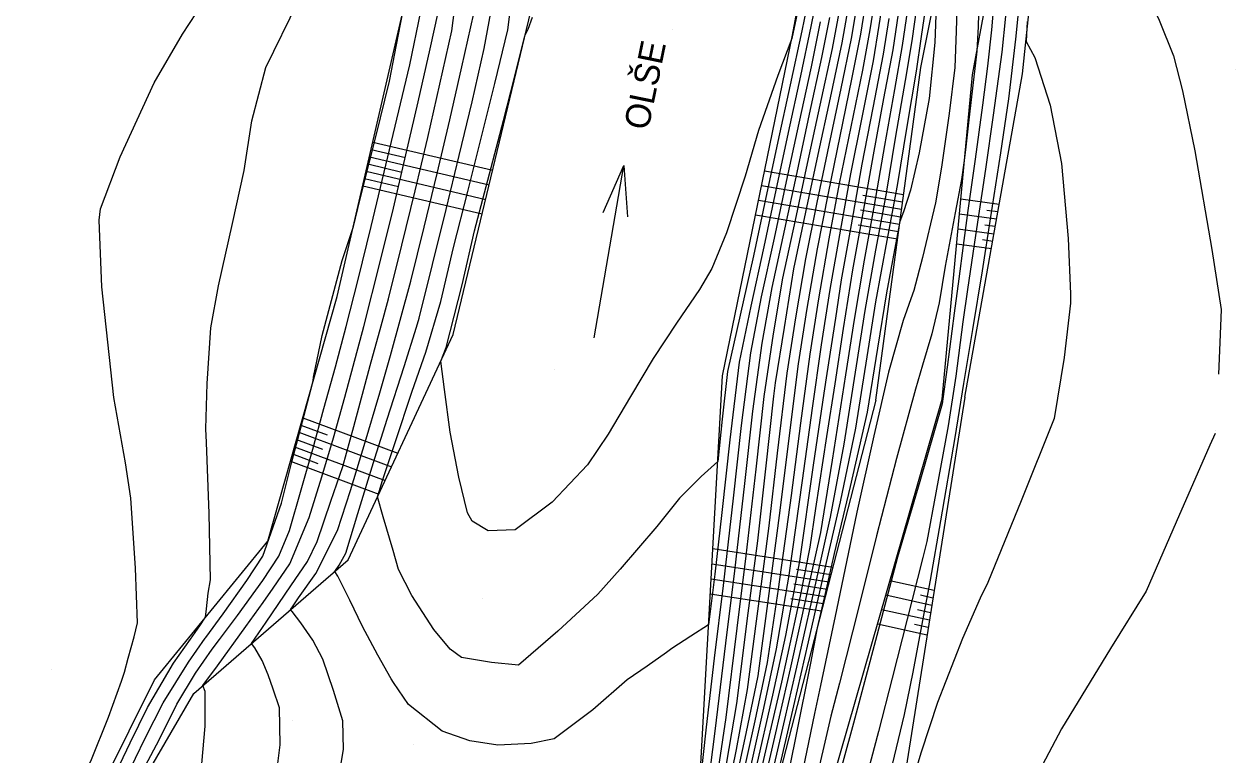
# Model space of a CAD drawing. Extents: x -448957 to -448612, y -1107690 to -1107245.
# Drawn here: x -448666.49 to -448617.96, y -1107347.3 to -1107318.02 of the extents above; entities that cross this region are included whole.
import ezdxf

# ---------------------------------------------------------------- set-up
doc = ezdxf.new("R2010")
doc.units = 0
for name, color, linetype in [('Default', 7, 'Continuous'), ('Vrstva 1', 7, 'Continuous'), ('Vrstva 14', 7, 'Continuous'), ('Vrstva 15', 7, 'Continuous'), ('Vrstva 16', 7, 'Continuous'), ('Vrstva 17', 7, 'Continuous'), ('Vrstva 45', 7, 'Continuous')]:
    doc.layers.add(name, color=color, linetype=linetype)

# ---------------------------------------------------------------- blocks, each defined once
blk = doc.blocks.new('POINT_DISPLAY')
at = {"layer": 'Default'}
blk.add_line((0, 0), (0, 0), dxfattribs=at)
blk = doc.blocks.new('TOK')
at = {"layer": 'Default'}
for p, q in [((-5, 50), (0, 70)), ((0, 0), (0, 70)), ((0, 70), (5, 50))]:
    blk.add_line(p, q, dxfattribs=at)

msp = doc.modelspace()

# ---------------------------------------------------------------- linework, layer by layer
at = {"layer": 'Vrstva 14'}
for p, q in [((-448635.721, -1107318.467), (-448634.176, -1107310.229)), ((-448630.579, -1107319.751), (-448628.858, -1107311.238)), ((-448628.507, -1107320.045), (-448626.884, -1107311.34)), ((-448626.501, -1107320.009), (-448625.591, -1107311.34)), ((-448653.948, -1107328.929), (-448651.01, -1107316.15)), ((-448649.301, -1107330.46), (-448646.198, -1107317.516)), ((-448638.523, -1107332.119), (-448635.721, -1107318.467)), ((-448632.378, -1107333.085), (-448630.579, -1107319.751)), ((-448629.722, -1107333.044), (-448628.507, -1107320.045)), ((-448628.814, -1107332.973), (-448626.501, -1107320.009)), ((-448656.73, -1107338.733), (-448653.948, -1107328.929)), ((-448653.513, -1107339.486), (-448649.301, -1107330.46)), ((-448639.5, -1107349.716), (-448638.523, -1107332.119)), ((-448632.378, -1107333.085), (-448636.968, -1107350.917)), ((-448635.081, -1107351.7), (-448629.722, -1107333.044)), ((-448628.814, -1107332.973), (-448631.997, -1107353.013)), ((-448661.274, -1107344.294), (-448656.73, -1107338.733)), ((-448659.693, -1107344.838), (-448653.513, -1107339.486)), ((-448665.508, -1107352.833), (-448661.274, -1107344.294)), ((-448664.543, -1107353.162), (-448659.693, -1107344.838))]:
    msp.add_line(p, q, dxfattribs=at)
at = {"layer": 'Vrstva 15'}
for p, q in [((-448652.527, -1107322.747), (-448647.722, -1107323.875)), ((-448652.661, -1107323.332), (-448647.862, -1107324.458)), ((-448652.594, -1107323.039), (-448651.223, -1107323.361)), ((-448652.728, -1107323.624), (-448651.359, -1107323.946)), ((-448652.863, -1107324.209), (-448651.495, -1107324.53)), ((-448652.796, -1107323.916), (-448648.002, -1107325.042)), ((-448631.268, -1107324.858), (-448636.839, -1107323.912)), ((-448652.93, -1107324.501), (-448648.142, -1107325.625)), ((-448631.348, -1107325.453), (-448636.959, -1107324.5)), ((-448631.429, -1107326.048), (-448637.08, -1107325.088)), ((-448631.308, -1107325.156), (-448632.9, -1107324.885)), ((-448627.436, -1107325.247), (-448628.974, -1107325.039)), ((-448631.509, -1107326.643), (-448637.201, -1107325.676)), ((-448631.388, -1107325.751), (-448632.992, -1107325.478)), ((-448627.541, -1107325.839), (-448629.03, -1107325.637)), ((-448627.488, -1107325.543), (-448627.928, -1107325.483)), ((-448631.469, -1107326.346), (-448633.083, -1107326.071)), ((-448627.647, -1107326.43), (-448629.086, -1107326.234)), ((-448627.594, -1107326.134), (-448628.019, -1107326.076)), ((-448627.699, -1107326.725), (-448628.11, -1107326.669)), ((-448627.752, -1107327.021), (-448629.141, -1107326.832)), ((-448655.329, -1107333.796), (-448651.52, -1107335.215)), ((-448655.493, -1107334.375), (-448651.774, -1107335.76)), ((-448655.411, -1107334.085), (-448654.349, -1107334.481)), ((-448655.658, -1107334.954), (-448652.029, -1107336.306)), ((-448655.576, -1107334.664), (-448654.539, -1107335.051)), ((-448655.74, -1107335.244), (-448654.729, -1107335.62)), ((-448655.822, -1107335.533), (-448652.283, -1107336.851)), ((-448634.105, -1107339.796), (-448638.908, -1107339.052)), ((-448634.256, -1107340.38), (-448638.941, -1107339.654)), ((-448634.181, -1107340.088), (-448635.553, -1107339.875)), ((-448634.406, -1107340.964), (-448638.975, -1107340.256)), ((-448630.045, -1107340.721), (-448631.814, -1107340.328)), ((-448634.331, -1107340.672), (-448635.67, -1107340.465)), ((-448634.556, -1107341.548), (-448639.008, -1107340.858)), ((-448634.481, -1107341.256), (-448635.787, -1107341.054)), ((-448630.139, -1107341.315), (-448631.98, -1107340.906)), ((-448630.092, -1107341.018), (-448630.597, -1107340.906)), ((-448630.233, -1107341.909), (-448632.146, -1107341.484)), ((-448630.186, -1107341.612), (-448630.712, -1107341.495)), ((-448630.328, -1107342.502), (-448632.312, -1107342.061)), ((-448630.28, -1107342.205), (-448630.827, -1107342.084))]:
    msp.add_line(p, q, dxfattribs=at)
at = {"layer": 'Vrstva 16'}
for points in [[(-448629.106, -1107316.523), (-448629.157, -1107318.305), (-448629.22, -1107319.755), (-448629.449, -1107321.594), (-448629.744, -1107323.748), (-448629.994, -1107325.182), (-448630.505, -1107327.371), (-448630.863, -1107328.699), (-448630.908, -1107328.847), (-448631.284, -1107329.89), (-448631.877, -1107331.97), (-448632.455, -1107334.512), (-448633.135, -1107337.575), (-448633.956, -1107341.492), (-448634.593, -1107344.517), (-448634.838, -1107345.644), (-448635.47, -1107348.671)], [(-448634.697, -1107316.72), (-448634.979, -1107318.108), (-448635.391, -1107320.087), (-448635.886, -1107322.356), (-448636.383, -1107324.678), (-448636.866, -1107326.949), (-448637.392, -1107329.316), (-448637.859, -1107331.566), (-448638.229, -1107334.684), (-448638.543, -1107337.593), (-448638.834, -1107340.058), (-448639.077, -1107342.091), (-448639.783, -1107342.548), (-448640.547, -1107343.043), (-448640.766, -1107343.197), (-448641.533, -1107343.748), (-448642.341, -1107344.302), (-448643.718, -1107345.501), (-448645.268, -1107346.657), (-448646.186, -1107346.846), (-448647.512, -1107346.918), (-448648.644, -1107346.739), (-448649.754, -1107346.356), (-448651.09, -1107345.278), (-448651.698, -1107344.404), (-448651.792, -1107344.262), (-448652.329, -1107343.304), (-448652.943, -1107342.156), (-448653.443, -1107341.1), (-448653.927, -1107340.142), (-448654.047, -1107339.948), (-448653.869, -1107339.696), (-448653.612, -1107339.218), (-448653.12, -1107337.636), (-448652.447, -1107335.416), (-448651.951, -1107333.844), (-448651.274, -1107331.737), (-448650.771, -1107330.167), (-448650.663, -1107329.804), (-448650.135, -1107327.65), (-448649.586, -1107325.446), (-448649.068, -1107323.289), (-448648.553, -1107321.135), (-448648.062, -1107319.001), (-448647.632, -1107316.676)], [(-448662.412, -1107348.242), (-448661.639, -1107346.632), (-448660.924, -1107345.213), (-448659.909, -1107343.584), (-448659.234, -1107342.629), (-448659.214, -1107342.601), (-448658.521, -1107341.652), (-448657.573, -1107340.317), (-448656.932, -1107339.341), (-448656.178, -1107337.212), (-448655.769, -1107335.565), (-448655.34, -1107333.946), (-448654.937, -1107332.414), (-448654.92, -1107332.301), (-448654.899, -1107332.173), (-448654.55, -1107330.499), (-448653.755, -1107327.486), (-448653.305, -1107326.131), (-448653.126, -1107325.403), (-448652.941, -1107324.648), (-448652.41, -1107322.53), (-448651.854, -1107320.303), (-448651.576, -1107318.852), (-448651.329, -1107317.537)], [(-448633.126, -1107317.166), (-448633.371, -1107318.595), (-448633.78, -1107320.603), (-448634.262, -1107322.875), (-448634.744, -1107325.173), (-448635.203, -1107327.425), (-448635.597, -1107329.794), (-448635.95, -1107332.008), (-448636.331, -1107335.215), (-448636.664, -1107338.121), (-448636.788, -1107339.044), (-448637.172, -1107341.943), (-448637.526, -1107344.687), (-448637.968, -1107347.084), (-448638.444, -1107349.382)], [(-448631.487, -1107317.61), (-448631.7, -1107319.047), (-448632.067, -1107321.003), (-448632.491, -1107323.26), (-448632.908, -1107325.665), (-448633.309, -1107327.872), (-448633.686, -1107330.214), (-448634.027, -1107332.429), (-448634.356, -1107334.547), (-448634.794, -1107337.436), (-448635.017, -1107338.98), (-448635.41, -1107340.943), (-448635.935, -1107343.353), (-448636.164, -1107344.395), (-448636.757, -1107346.965), (-448637.451, -1107349.97)], [(-448626.316, -1107317.915), (-448626.365, -1107318.711), (-448626.015, -1107319.352), (-448625.399, -1107321.27), (-448624.939, -1107323.608), (-448624.673, -1107326.604), (-448624.587, -1107328.827), (-448624.585, -1107329.204), (-448624.842, -1107331.382), (-448625.243, -1107333.824), (-448626.562, -1107337.126), (-448627.898, -1107340.389), (-448628.207, -1107341.018), (-448628.903, -1107342.638), (-448629.907, -1107345.198), (-448630.567, -1107347.19), (-448631.215, -1107349.365)]]:
    msp.add_lwpolyline(points, dxfattribs=at)
at = {"layer": 'Vrstva 17'}
for points in [[(-448617.964, -1107313.829), (-448618.273, -1107313.944), (-448619.544, -1107314.14), (-448620.66, -1107314.171), (-448621.165, -1107314.233), (-448622.028, -1107314.546), (-448621.957, -1107315.886), (-448621.031, -1107317.86), (-448620.462, -1107319.291), (-448620.091, -1107320.697), (-448619.61, -1107323.098), (-448618.918, -1107327.048), (-448618.552, -1107329.451), (-448618.602, -1107330.773), (-448618.658, -1107332.053)], [(-448656.419, -1107348.395), (-448656.237, -1107346.894), (-448656.263, -1107345.417), (-448656.52, -1107344.673), (-448656.722, -1107344.095), (-448656.959, -1107343.525), (-448657.245, -1107343.019), (-448657.384, -1107342.839), (-448656.801, -1107341.979), (-448655.813, -1107340.533), (-448655.141, -1107339.558), (-448654.748, -1107338.746), (-448654.203, -1107337.131), (-448653.729, -1107335.747), (-448653.292, -1107334.149), (-448652.629, -1107331.705), (-448652.186, -1107330.115), (-448651.892, -1107329.031), (-448651.359, -1107326.879), (-448650.823, -1107324.694), (-448650.326, -1107322.557), (-448649.837, -1107320.428), (-448649.36, -1107318.294), (-448649.07, -1107315.999)], [(-448628.23, -1107316.081), (-448628.276, -1107318.113), (-448628.33, -1107319.097), (-448628.384, -1107319.57), (-448628.48, -1107320.353), (-448628.655, -1107321.858), (-448628.788, -1107323.054), (-448628.859, -1107323.583), (-448628.947, -1107324.241), (-448629.202, -1107325.586), (-448629.602, -1107327.725), (-448629.849, -1107329.188), (-448630.142, -1107330.433), (-448630.505, -1107331.685), (-448630.797, -1107332.647), (-448631.554, -1107335.42), (-448632.354, -1107338.528), (-448633.048, -1107341.316), (-448633.839, -1107344.424), (-448634.184, -1107345.747), (-448634.881, -1107348.762)], [(-448627.534, -1107315.743), (-448627.745, -1107318.25), (-448627.906, -1107319.699), (-448628.111, -1107321.267), (-448628.405, -1107323.426), (-448628.578, -1107324.652), (-448628.694, -1107325.486), (-448628.879, -1107326.888), (-448629.06, -1107328.226), (-448629.244, -1107329.597), (-448629.526, -1107331.77), (-448629.728, -1107333.229), (-448630.622, -1107336.345), (-448631.507, -1107339.38), (-448632.34, -1107342.515), (-448633.28, -1107346.036), (-448634.134, -1107349.162)], [(-448635.06, -1107316.91), (-448635.349, -1107318.287), (-448635.811, -1107320.45), (-448636.307, -1107322.718), (-448636.8, -1107325.035), (-448637.283, -1107327.306), (-448637.817, -1107329.687), (-448638.315, -1107331.946), (-448638.53, -1107333.844), (-448638.713, -1107335.542), (-448639.376, -1107336.147), (-448640.239, -1107337.022), (-448641.154, -1107338.146), (-448642.616, -1107339.866), (-448643.51, -1107340.867), (-448645.112, -1107342.346), (-448646.689, -1107343.707), (-448647.776, -1107343.604), (-448648.973, -1107343.404), (-448649.423, -1107343.063), (-448650.075, -1107342.283), (-448650.968, -1107340.92), (-448651.493, -1107339.87), (-448651.716, -1107339.114), (-448652.105, -1107337.765), (-448652.335, -1107336.962), (-448652.258, -1107336.708), (-448652.149, -1107336.351), (-448651.628, -1107334.787), (-448650.949, -1107332.724), (-448650.404, -1107331.168), (-448649.805, -1107329.133), (-448649.294, -1107326.973), (-448648.721, -1107324.733), (-448648.181, -1107322.584), (-448647.64, -1107320.392), (-448647.12, -1107318.251), (-448646.907, -1107316.567)], [(-448667.516, -1107353.349), (-448666.237, -1107351.73), (-448665.263, -1107350.375), (-448664.557, -1107348.977), (-448663.821, -1107347.557), (-448663.111, -1107345.787), (-448662.585, -1107344.345), (-448662.505, -1107344.114), (-448662.472, -1107343.99), (-448662.32, -1107343.423), (-448662.081, -1107342.57), (-448661.948, -1107342.013), (-448662.027, -1107339.815), (-448662.213, -1107337.02), (-448662.425, -1107335.598), (-448662.903, -1107332.976), (-448663.381, -1107328.546), (-448663.491, -1107325.878), (-448663.429, -1107325.418), (-448662.646, -1107323.333), (-448661.288, -1107320.368), (-448660.143, -1107318.417), (-448659.03, -1107316.692)], [(-448659.377, -1107347.66), (-448659.245, -1107346.147), (-448659.236, -1107344.757), (-448659.33, -1107344.524), (-448658.741, -1107343.728), (-448657.613, -1107342.161), (-448656.922, -1107341.19), (-448656.521, -1107340.62), (-448655.855, -1107339.642), (-448655.068, -1107337.785), (-448654.565, -1107336.161), (-448654.098, -1107334.596), (-448653.645, -1107332.973), (-448653.308, -1107331.728), (-448652.885, -1107330.132), (-448652.234, -1107327.547), (-448651.703, -1107325.4), (-448651.203, -1107323.256), (-448650.705, -1107321.128), (-448650.225, -1107319.012), (-448649.761, -1107316.875)], [(-448632.76, -1107316.989), (-448632.999, -1107318.42), (-448633.348, -1107320.231), (-448633.822, -1107322.505), (-448634.294, -1107324.788), (-448634.734, -1107327.027), (-448635.139, -1107329.412), (-448635.489, -1107331.627), (-448635.863, -1107334.612), (-448636.22, -1107337.514), (-448636.719, -1107341.231), (-448637.099, -1107344.132), (-448637.584, -1107346.451), (-448638.234, -1107349.477)], [(-448632.395, -1107316.812), (-448632.626, -1107318.245), (-448632.915, -1107319.859), (-448633.382, -1107322.134), (-448633.845, -1107324.403), (-448634.266, -1107326.628), (-448634.681, -1107329.031), (-448635.027, -1107331.246), (-448635.394, -1107334.009), (-448635.776, -1107336.908), (-448636.293, -1107340.668), (-448636.733, -1107343.596), (-448637.229, -1107345.939), (-448637.892, -1107348.96)], [(-448632.029, -1107316.635), (-448632.254, -1107318.069), (-448632.483, -1107319.487), (-448632.942, -1107321.764), (-448633.395, -1107324.018), (-448633.797, -1107326.23), (-448634.223, -1107328.649), (-448634.566, -1107330.865), (-448634.926, -1107333.406), (-448635.332, -1107336.301), (-448635.868, -1107340.105), (-448636.368, -1107343.059), (-448636.875, -1107345.428), (-448637.55, -1107348.442)], [(-448663.068, -1107348.554), (-448662.25, -1107346.826), (-448661.548, -1107345.401), (-448660.502, -1107343.623), (-448659.825, -1107342.668), (-448659.452, -1107342.125), (-448659.222, -1107341.783), (-448659.192, -1107341.457), (-448659.123, -1107340.816), (-448659.03, -1107340.284), (-448659.074, -1107337.63), (-448659.185, -1107334.79), (-448659.211, -1107334.24), (-448659.162, -1107332.416), (-448659.016, -1107330.191), (-448658.705, -1107328.505), (-448658.144, -1107326.014), (-448657.672, -1107323.879), (-448657.377, -1107321.891), (-448656.813, -1107319.76), (-448655.517, -1107317.118)], [(-448662.067, -1107348.559), (-448661.083, -1107346.696), (-448660.378, -1107345.273), (-448659.624, -1107344.024), (-448658.953, -1107343.068), (-448658.672, -1107342.675), (-448657.946, -1107341.715), (-448656.933, -1107340.317), (-448656.283, -1107339.336), (-448655.856, -1107338.31), (-448655.398, -1107336.675), (-448654.934, -1107335.053), (-448654.484, -1107333.416), (-448654.022, -1107331.751), (-448653.595, -1107330.138), (-448653.118, -1107328.259), (-448652.592, -1107326.126), (-448652.072, -1107323.952), (-448651.558, -1107321.829), (-448651.04, -1107319.657), (-448650.603, -1107317.512)], [(-448635.423, -1107317.1), (-448635.733, -1107318.532), (-448635.747, -1107318.596), (-448636.306, -1107320.08), (-448637.077, -1107322.276), (-448637.607, -1107324.116), (-448638.361, -1107326.378), (-448638.948, -1107327.817), (-448639.436, -1107328.649), (-448640.357, -1107330), (-448641.301, -1107331.414), (-448642.205, -1107332.941), (-448643.106, -1107334.451), (-448643.924, -1107335.684), (-448645.346, -1107337.175), (-448646.829, -1107338.288), (-448647.9, -1107338.318), (-448648.55, -1107337.933), (-448648.734, -1107337.607), (-448649.084, -1107336.176), (-448649.434, -1107334.371), (-448649.657, -1107332.667), (-448649.798, -1107331.525), (-448649.594, -1107330.978), (-448648.946, -1107328.461), (-448648.453, -1107326.296), (-448647.857, -1107324.021), (-448647.293, -1107321.879), (-448646.855, -1107320.152), (-448646.431, -1107318.488), (-448646.3, -1107318.224), (-448646.132, -1107317.745)], [(-448633.492, -1107317.343), (-448633.743, -1107318.771), (-448634.212, -1107320.975), (-448634.702, -1107323.245), (-448635.194, -1107325.559), (-448635.672, -1107327.824), (-448636.055, -1107330.176), (-448636.412, -1107332.389), (-448636.475, -1107332.926), (-448636.797, -1107335.834), (-448637.12, -1107338.722), (-448637.5, -1107341.621), (-448637.958, -1107345.243), (-448638.463, -1107348.227)], [(-448631.109, -1107317.433), (-448631.32, -1107318.871), (-448631.634, -1107320.638), (-448632.038, -1107322.883), (-448632.445, -1107325.272), (-448632.853, -1107327.477), (-448633.253, -1107329.857), (-448633.599, -1107332.072), (-448634.133, -1107335.498), (-448634.602, -1107338.396), (-448635.139, -1107340.838), (-448635.807, -1107343.856), (-448636.398, -1107346.422), (-448637.093, -1107349.428)], [(-448630.732, -1107317.255), (-448630.94, -1107318.694), (-448631.201, -1107320.274), (-448631.586, -1107322.506), (-448631.983, -1107324.879), (-448632.396, -1107327.083), (-448632.821, -1107329.5), (-448633.171, -1107331.714), (-448633.666, -1107334.856), (-448634.202, -1107337.779), (-448634.775, -1107340.302), (-448635.449, -1107343.317), (-448636.039, -1107345.88), (-448636.735, -1107348.885)], [(-448630.355, -1107317.078), (-448630.56, -1107318.517), (-448630.767, -1107319.91), (-448631.133, -1107322.128), (-448631.52, -1107324.485), (-448631.939, -1107326.689), (-448632.388, -1107329.143), (-448632.744, -1107331.357), (-448633.198, -1107334.213), (-448633.802, -1107337.161), (-448634.41, -1107339.767), (-448635.091, -1107342.778), (-448635.679, -1107345.337), (-448636.376, -1107348.342)], [(-448629.96, -1107317.303), (-448630.023, -1107318.753), (-448630.247, -1107320.997), (-448630.642, -1107323.181), (-448630.989, -1107324.671), (-448631.265, -1107325.542), (-448631.413, -1107325.934), (-448631.671, -1107327.275), (-448631.956, -1107328.786), (-448632.316, -1107330.999), (-448632.731, -1107333.57), (-448633.402, -1107336.543), (-448634.045, -1107339.231), (-448634.412, -1107340.84), (-448634.726, -1107342.207), (-448634.998, -1107343.625), (-448635.579, -1107346.555), (-448636.193, -1107349.59)], [(-448626.642, -1107317.167), (-448626.784, -1107318.616), (-448627.07, -1107321.014), (-448627.389, -1107323.173), (-448627.785, -1107325.748), (-448628.121, -1107327.908), (-448628.511, -1107330.253), (-448628.864, -1107332.416), (-448629.21, -1107334.584), (-448629.788, -1107337.928), (-448630.208, -1107340.303), (-448630.505, -1107341.913), (-448630.891, -1107343.986), (-448631.248, -1107345.684), (-448631.811, -1107348.029)], [(-448653.967, -1107348.682), (-448653.7, -1107347.089), (-448653.72, -1107345.944), (-448654.099, -1107344.723), (-448654.529, -1107343.466), (-448654.924, -1107342.7), (-448655.409, -1107342.01), (-448655.759, -1107341.56), (-448655.819, -1107341.483), (-448655.74, -1107341.366), (-448655.497, -1107341.013), (-448654.812, -1107340.041), (-448653.946, -1107338.312), (-448653.417, -1107336.713), (-448652.793, -1107334.638), (-448652.322, -1107333.058), (-448652.276, -1107332.886), (-448651.813, -1107331.303), (-448651.002, -1107328.314), (-448650.469, -1107326.162), (-448649.949, -1107324), (-448649.443, -1107321.85), (-448648.959, -1107319.728), (-448648.477, -1107317.595)], [(-448634.609, -1107317.929), (-448634.97, -1107319.725), (-448635.465, -1107321.994), (-448635.966, -1107324.322), (-448636.449, -1107326.593), (-448636.967, -1107328.946), (-448637.403, -1107331.186), (-448637.775, -1107334.103), (-448638.091, -1107337.012), (-448638.5, -1107340.521), (-448638.854, -1107343.423), (-448639.174, -1107346.198), (-448639.433, -1107348.504)], [(-448634.238, -1107317.75), (-448634.55, -1107319.363), (-448635.044, -1107321.631), (-448635.549, -1107323.965), (-448636.033, -1107326.236), (-448636.541, -1107328.576), (-448636.947, -1107330.805), (-448637.321, -1107333.523), (-448637.639, -1107336.431), (-448638.04, -1107339.921), (-448638.402, -1107342.823), (-448638.822, -1107346.355), (-448639.2, -1107349.285)], [(-448633.868, -1107317.571), (-448634.13, -1107319.001), (-448634.624, -1107321.269), (-448635.132, -1107323.609), (-448635.616, -1107325.88), (-448636.116, -1107328.206), (-448636.491, -1107330.425), (-448636.867, -1107332.942), (-448637.187, -1107335.851), (-448637.58, -1107339.322), (-448637.951, -1107342.222), (-448638.39, -1107345.799), (-448638.832, -1107348.756)], [(-448631.864, -1107317.788), (-448632.08, -1107319.224), (-448632.5, -1107321.367), (-448632.943, -1107323.637), (-448633.371, -1107326.058), (-448633.766, -1107328.266), (-448634.001, -1107329.8), (-448634.339, -1107332.016), (-448634.458, -1107332.803), (-448634.888, -1107335.694), (-448635.443, -1107339.542), (-448636.003, -1107342.523), (-448636.52, -1107344.916), (-448637.202, -1107347.896)], [(-448627.191, -1107317.698), (-448627.339, -1107319.147), (-448627.674, -1107321.673), (-448627.987, -1107323.832), (-448628.384, -1107326.491), (-448628.713, -1107328.651), (-448628.895, -1107329.953), (-448629.181, -1107332.126), (-448629.479, -1107334.119), (-448629.97, -1107336.799), (-448630.342, -1107338.751), (-448630.493, -1107339.398), (-448630.928, -1107341.081), (-448631.729, -1107344.23), (-448632.269, -1107346.365), (-448633.107, -1107349.497)], [(-448618.788, -1107334.419), (-448619, -1107334.896), (-448620.348, -1107337.975), (-448621.554, -1107340.737), (-448622.982, -1107343.045), (-448624.946, -1107346.261), (-448626.341, -1107348.916)]]:
    msp.add_lwpolyline(points, dxfattribs=at)

# ---------------------------------------------------------------- block references
at = {"layer": 'Vrstva 1', "xscale": 0.1, "yscale": 0.10000000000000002}
for p in [(-448635.721, -1107318.467), (-448630.579, -1107319.751), (-448628.507, -1107320.045), (-448626.501, -1107320.009), (-448653.948, -1107328.929), (-448649.301, -1107330.46), (-448638.523, -1107332.119), (-448632.378, -1107333.085), (-448629.722, -1107333.044), (-448628.814, -1107332.973), (-448656.73, -1107338.733), (-448653.513, -1107339.486), (-448661.274, -1107344.294), (-448659.693, -1107344.838)]:
    msp.add_blockref('POINT_DISPLAY', p, dxfattribs=at)
at = {"layer": 'Vrstva 14', "xscale": 0.1, "yscale": 0.10000000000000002}
for p in [(-448640.524, -1107318.239), (-448617.968, -1107319.842), (-448663.835, -1107325.517), (-448645.25, -1107331.873), (-448618.786, -1107334.318), (-448648.119, -1107341.025), (-448665.388, -1107343.872), (-448655.736, -1107345.932), (-448650.882, -1107346.881)]:
    msp.add_blockref('POINT_DISPLAY', p, dxfattribs=at)
at = {"layer": 'Vrstva 45', "xscale": 0.10000000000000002, "yscale": 0.09999999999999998, "rotation": -9.82733959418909}
msp.add_blockref('TOK', (-448643.666, -1107330.584), dxfattribs=at)

# ---------------------------------------------------------------- texts
at = {"layer": 'Vrstva 45'}
msp.add_text('OLŠE', height=1, rotation=78.4014, dxfattribs=at).set_placement((-448641.496, -1107322.306))

doc.saveas('drawing.dxf')
